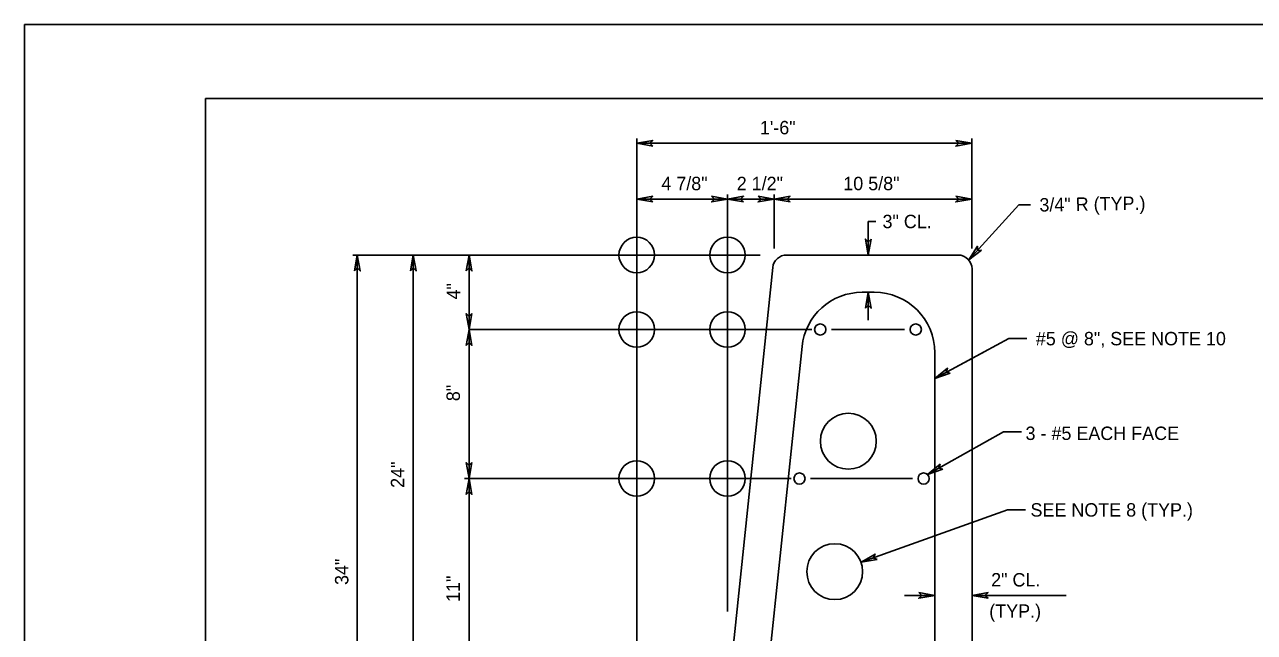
# Model space of a CAD drawing. Extents: x -32.9 to -15.8, y -6.5 to 4.5.
# Drawn here: x -24.32 to -18.82, y 1.78 to 4.5 of the extents above; entities that cross this region are included whole.
import ezdxf

# ---------------------------------------------------------------- set-up
doc = ezdxf.new("R2010")
doc.units = 0
for name, color, linetype in [('ANNO-WOUT', 7, 'Continuous'), ('BORD-LINE', 7, 'Continuous'), ('DETL-DIMS', 7, 'Continuous'), ('DETL-NOTE', 7, 'Continuous'), ('Level 10', 7, 'Continuous'), ('Level 12', 7, 'Continuous'), ('SUPR-PARA_P', 7, 'Continuous'), ('SUPR-RFRC', 7, 'Continuous'), ('USER-CLIP', 7, 'Continuous')]:
    doc.layers.add(name, color=color, linetype=linetype)

msp = doc.modelspace()

# ---------------------------------------------------------------- linework, layer by layer
at = {"layer": 'ANNO-WOUT'}
for centre in [(-21.5854, 3.4724), (-21.1791, 3.4724), (-21.5854, 3.1391), (-21.1791, 3.1391), (-21.5854, 2.4724), (-21.1791, 2.4724)]:
    msp.add_circle(centre, 0.0795, dxfattribs=at)
at = {"layer": 'BORD-LINE'}
msp.add_lwpolyline([(-23.5151, 4.1733), (-16.1409, 4.1733), (-16.1409, -6.1798), (-23.5151, -6.1798)], close=True, dxfattribs=at)
at = {"layer": 'DETL-DIMS'}
for p, q in [((-21.5854, 3.9724), (-21.5139, 3.9851)), ((-21.5854, 3.9724), (-21.5139, 3.9599)), ((-21.5274, 3.9724), (-21.5139, 3.9851)), ((-21.5139, 3.9599), (-21.5274, 3.9724)), ((-20.0867, 3.9724), (-20.1582, 3.985)), ((-20.1582, 3.985), (-20.1447, 3.9724)), ((-20.0867, 3.9724), (-20.1582, 3.9598)), ((-20.1447, 3.9724), (-20.1582, 3.9598)), ((-21.5854, 3.7224), (-21.5139, 3.7351)), ((-21.5854, 3.7224), (-21.5139, 3.7099)), ((-21.5274, 3.7224), (-21.5139, 3.7351)), ((-21.5139, 3.7099), (-21.5274, 3.7224)), ((-21.1791, 3.7224), (-21.2506, 3.735)), ((-21.2506, 3.735), (-21.2371, 3.7224)), ((-21.1791, 3.7224), (-21.2506, 3.7098)), ((-21.2371, 3.7224), (-21.2506, 3.7098)), ((-21.1791, 3.7224), (-21.1076, 3.7351)), ((-21.1791, 3.7224), (-21.1076, 3.7099)), ((-21.1211, 3.7224), (-21.1076, 3.7351)), ((-21.1076, 3.7099), (-21.1211, 3.7224)), ((-20.9708, 3.7224), (-21.0423, 3.735)), ((-21.0423, 3.735), (-21.0288, 3.7224)), ((-20.9708, 3.7224), (-21.0423, 3.7098)), ((-21.0288, 3.7224), (-21.0423, 3.7098)), ((-20.9708, 3.7224), (-20.8993, 3.7351)), ((-20.9708, 3.7224), (-20.8993, 3.7099)), ((-20.9128, 3.7224), (-20.8993, 3.7351)), ((-20.8993, 3.7099), (-20.9128, 3.7224)), ((-20.0867, 3.7224), (-20.1582, 3.735)), ((-20.1582, 3.735), (-20.1447, 3.7224)), ((-20.0867, 3.7224), (-20.1582, 3.7098)), ((-20.1447, 3.7224), (-20.1582, 3.7098)), ((-20.5497, 3.4724), (-20.5624, 3.544)), ((-20.5497, 3.5304), (-20.5624, 3.544)), ((-20.5497, 3.4724), (-20.5372, 3.5439)), ((-20.5372, 3.5439), (-20.5497, 3.5304)), ((-22.8354, 3.4724), (-22.8479, 3.401)), ((-22.8354, 3.4724), (-22.8227, 3.4009)), ((-22.5854, 3.4724), (-22.5979, 3.401)), ((-22.5854, 3.4724), (-22.5727, 3.4009)), ((-22.3354, 3.4724), (-22.3479, 3.401)), ((-22.3354, 3.4724), (-22.3227, 3.4009)), ((-20.1, 3.4501), (-20.0612, 3.5115)), ((-20.1, 3.4501), (-20.0426, 3.4945)), ((-20.0609, 3.493), (-20.0612, 3.5115)), ((-20.0426, 3.4945), (-20.0609, 3.493)), ((-22.8479, 3.401), (-22.8354, 3.4144)), ((-22.8354, 3.4144), (-22.8227, 3.4009)), ((-22.5979, 3.401), (-22.5854, 3.4144)), ((-22.5854, 3.4144), (-22.5727, 3.4009)), ((-22.3479, 3.401), (-22.3354, 3.4144)), ((-22.3354, 3.4144), (-22.3227, 3.4009)), ((-20.5497, 3.3058), (-20.5623, 3.2343)), ((-20.5497, 3.3058), (-20.5371, 3.2343)), ((-20.5623, 3.2343), (-20.5497, 3.2478)), ((-20.5497, 3.2478), (-20.5371, 3.2343)), ((-22.3354, 3.1391), (-22.3481, 3.2106)), ((-22.3354, 3.1971), (-22.3481, 3.2106)), ((-22.3354, 3.1391), (-22.3229, 3.2106)), ((-22.3229, 3.2106), (-22.3354, 3.1971)), ((-22.3354, 3.1391), (-22.3479, 3.0676)), ((-22.3354, 3.1391), (-22.3227, 3.0676)), ((-22.3479, 3.0676), (-22.3354, 3.0811)), ((-22.3354, 3.0811), (-22.3227, 3.0676)), ((-20.2519, 2.9205), (-20.1949, 2.9655)), ((-20.2519, 2.9205), (-20.1949, 2.9655)), ((-20.2519, 2.9205), (-20.183, 2.9433)), ((-20.2519, 2.9205), (-20.183, 2.9433)), ((-20.2008, 2.9479), (-20.1949, 2.9655)), ((-20.2008, 2.9479), (-20.1949, 2.9655)), ((-20.183, 2.9433), (-20.2008, 2.9479)), ((-20.183, 2.9433), (-20.2008, 2.9479)), ((-22.3354, 2.4724), (-22.3481, 2.544)), ((-22.3354, 2.5304), (-22.3481, 2.544)), ((-22.3354, 2.4724), (-22.3229, 2.5439)), ((-22.3229, 2.5439), (-22.3354, 2.5304)), ((-20.2844, 2.4901), (-20.2283, 2.5363)), ((-20.2339, 2.5187), (-20.2283, 2.5363)), ((-20.2844, 2.4901), (-20.216, 2.5144)), ((-20.216, 2.5144), (-20.2339, 2.5187)), ((-22.3354, 2.4724), (-22.3479, 2.401)), ((-22.3354, 2.4724), (-22.3227, 2.4009)), ((-22.3479, 2.401), (-22.3354, 2.4144)), ((-22.3354, 2.4144), (-22.3227, 2.4009)), ((-20.582, 2.0979), (-20.5189, 2.134)), ((-20.582, 2.0979), (-20.5104, 2.1102)), ((-20.5274, 2.1175), (-20.5189, 2.134)), ((-20.5104, 2.1102), (-20.5274, 2.1175)), ((-20.252, 1.9493), (-20.3236, 1.9366)), ((-20.31, 1.9493), (-20.3236, 1.9366)), ((-20.252, 1.9493), (-20.3236, 1.9366)), ((-20.31, 1.9493), (-20.3236, 1.9366)), ((-20.252, 1.9493), (-20.3235, 1.9618)), ((-20.3235, 1.9618), (-20.31, 1.9493)), ((-20.252, 1.9493), (-20.3235, 1.9618)), ((-20.3235, 1.9618), (-20.31, 1.9493)), ((-20.0854, 1.9493), (-20.0139, 1.962)), ((-20.0854, 1.9493), (-20.0139, 1.962)), ((-20.0854, 1.9493), (-20.0139, 1.9368)), ((-20.0854, 1.9493), (-20.0139, 1.9368)), ((-20.0274, 1.9493), (-20.0139, 1.962)), ((-20.0274, 1.9493), (-20.0139, 1.962)), ((-20.0139, 1.9368), (-20.0274, 1.9493)), ((-20.0139, 1.9368), (-20.0274, 1.9493))]:
    msp.add_line(p, q, dxfattribs=at)
for points in [[(-21.5139, 3.9599), (-21.5854, 3.9724), (-21.5139, 3.9851), (-21.5274, 3.9724)], [(-20.1582, 3.985), (-20.0867, 3.9724), (-20.1582, 3.9598), (-20.1447, 3.9724)], [(-21.5139, 3.7099), (-21.5854, 3.7224), (-21.5139, 3.7351), (-21.5274, 3.7224)], [(-21.2506, 3.735), (-21.1791, 3.7224), (-21.2506, 3.7098), (-21.2371, 3.7224)], [(-21.1076, 3.7099), (-21.1791, 3.7224), (-21.1076, 3.7351), (-21.1211, 3.7224)], [(-21.0423, 3.735), (-20.9708, 3.7224), (-21.0423, 3.7098), (-21.0288, 3.7224)], [(-20.8993, 3.7099), (-20.9708, 3.7224), (-20.8993, 3.7351), (-20.9128, 3.7224)], [(-20.1582, 3.735), (-20.0867, 3.7224), (-20.1582, 3.7098), (-20.1447, 3.7224)], [(-20.5372, 3.5439), (-20.5497, 3.4724), (-20.5624, 3.544), (-20.5497, 3.5304)], [(-22.8479, 3.401), (-22.8354, 3.4724), (-22.8227, 3.4009), (-22.8354, 3.4144)], [(-22.5979, 3.401), (-22.5854, 3.4724), (-22.5727, 3.4009), (-22.5854, 3.4144)], [(-22.3479, 3.401), (-22.3354, 3.4724), (-22.3227, 3.4009), (-22.3354, 3.4144)], [(-20.0426, 3.4945), (-20.1, 3.4501), (-20.0612, 3.5115), (-20.0609, 3.493)], [(-20.5623, 3.2343), (-20.5497, 3.3058), (-20.5371, 3.2343), (-20.5497, 3.2478)], [(-22.3229, 3.2106), (-22.3354, 3.1391), (-22.3481, 3.2106), (-22.3354, 3.1971)], [(-22.3479, 3.0676), (-22.3354, 3.1391), (-22.3227, 3.0676), (-22.3354, 3.0811)], [(-20.183, 2.9433), (-20.2519, 2.9205), (-20.1949, 2.9655), (-20.2008, 2.9479)], [(-20.183, 2.9433), (-20.2519, 2.9205), (-20.1949, 2.9655), (-20.2008, 2.9479)], [(-22.3229, 2.5439), (-22.3354, 2.4724), (-22.3481, 2.544), (-22.3354, 2.5304)], [(-20.216, 2.5144), (-20.2844, 2.4901), (-20.2283, 2.5363), (-20.2339, 2.5187)], [(-22.3479, 2.401), (-22.3354, 2.4724), (-22.3227, 2.4009), (-22.3354, 2.4144)], [(-20.5104, 2.1102), (-20.582, 2.0979), (-20.5189, 2.134), (-20.5274, 2.1175)], [(-20.3235, 1.9618), (-20.252, 1.9493), (-20.3236, 1.9366), (-20.31, 1.9493)], [(-20.3235, 1.9618), (-20.252, 1.9493), (-20.3236, 1.9366), (-20.31, 1.9493)], [(-20.0139, 1.9368), (-20.0854, 1.9493), (-20.0139, 1.962), (-20.0274, 1.9493)], [(-20.0139, 1.9368), (-20.0854, 1.9493), (-20.0139, 1.962), (-20.0274, 1.9493)]]:
    msp.add_lwpolyline(points, close=True, dxfattribs=at)
at = {"layer": 'Level 10'}
for p, q in [((-21.5854, 0.9491), (-21.5854, 3.9933)), ((-21.5854, 3.9724), (-20.0867, 3.9724)), ((-20.0867, 3.5017), (-20.0867, 3.9933)), ((-21.1791, 1.877), (-21.1791, 3.7433)), ((-20.9708, 3.5012), (-20.9708, 3.7433)), ((-21.5854, 3.7224), (-21.1791, 3.7224)), ((-21.1791, 3.7224), (-20.9708, 3.7224)), ((-20.9708, 3.7224), (-20.0867, 3.7224)), ((-19.8753, 3.6968), (-20.1, 3.4501)), ((-19.8753, 3.6968), (-19.824, 3.6968)), ((-20.5497, 3.4724), (-20.5497, 3.6224)), ((-20.5497, 3.6224), (-20.5159, 3.6224)), ((-21.0337, 3.4724), (-22.8562, 3.4724)), ((-22.8354, 3.4724), (-22.8354, 0.6391)), ((-22.5854, 1.4753), (-22.5854, 3.4724)), ((-22.3354, 3.1391), (-22.3354, 3.4724)), ((-20.5497, 3.1808), (-20.5497, 3.3058)), ((-22.3354, 2.4724), (-22.3354, 3.1391)), ((-20.8022, 3.1391), (-22.3354, 3.1391)), ((-21.627, 3.1391), (-21.8865, 3.1391)), ((-21.2208, 3.1391), (-21.5437, 3.1391)), ((-20.3869, 3.1391), (-20.7147, 3.1391)), ((-19.9211, 3.0983), (-20.2523, 2.9203)), ((-19.9211, 3.0983), (-19.8401, 3.0983)), ((-20.025, 3.0424), (-20.2523, 2.9203)), ((-19.9452, 2.6817), (-20.2844, 2.4901)), ((-19.9452, 2.6817), (-19.8642, 2.6817)), ((-22.3562, 2.4724), (-20.8948, 2.4724)), ((-22.3354, 1.5558), (-22.3354, 2.4724)), ((-20.8073, 2.4724), (-20.352, 2.4724)), ((-19.9274, 2.3322), (-20.582, 2.0979)), ((-19.9274, 2.3322), (-19.8463, 2.3322)), ((-20.3872, 1.9493), (-20.252, 1.9493)), ((-20.3872, 1.9493), (-20.252, 1.9493)), ((-19.6645, 1.9493), (-20.0854, 1.9493))]:
    msp.add_line(p, q, dxfattribs=at)
at = {"layer": 'SUPR-PARA_P'}
for p, q in [((-20.9145, 3.4724), (-20.1479, 3.4724)), ((-21.157, 1.6879), (-20.9767, 3.4164)), ((-20.0854, 0.6391), (-20.0854, 3.4099))]:
    msp.add_line(p, q, dxfattribs=at)
for centre in [(-20.6388, 2.6391), (-20.6997, 2.0558)]:
    msp.add_circle(centre, 0.125, dxfattribs=at)
for centre, start, end in [((-20.9145, 3.4099), 90, 174.0468), ((-20.1479, 3.4099), 0, 90)]:
    msp.add_arc(centre, 0.0625, start, end, dxfattribs=at)
at = {"layer": 'SUPR-RFRC'}
for p, q in [((-20.5766, 3.3058), (-20.5229, 3.3058)), ((-21.2812, -1.1109), (-20.846, 3.063)), ((-20.252, -1.1109), (-20.252, 3.0349))]:
    msp.add_line(p, q, dxfattribs=at)
for centre in [(-20.7647, 3.1391), (-20.3369, 3.1391), (-20.8573, 2.4724), (-20.302, 2.4724)]:
    msp.add_circle(centre, 0.025, dxfattribs=at)
for centre, start, end in [((-20.5766, 3.0349), 90, 174.0468), ((-20.5229, 3.0349), 0, 90)]:
    msp.add_arc(centre, 0.2708, start, end, dxfattribs=at)
at = {"layer": 'USER-CLIP'}
msp.add_lwpolyline([(-15.824, 4.5033), (-24.324, 4.5033), (-24.324, -6.4967), (-15.824, -6.4967)], close=True, dxfattribs=at)

# ---------------------------------------------------------------- texts
at = {"layer": 'DETL-NOTE'}
msp.add_text('3" CL.', height=0.06001, dxfattribs=at).set_placement((-20.4859, 3.5924))
at = {"layer": 'Level 12'}
for s, p in [('1\'-6"', (-21.0344, 4.0124)), ('4 7/8"', (-21.4753, 3.7624)), ('2 1/2"', (-21.1381, 3.7623)), ('10 5/8"', (-20.6614, 3.7624)), ('#5 @ 8", SEE NOTE 10', (-19.8, 3.0683)), ('3 - #5 EACH FACE', (-19.8461, 2.6448)), ('SEE NOTE 8 (TYP.)', (-19.8239, 2.302)), ('2" CL.', (-20, 1.9893)), ('(TYP.)', (-20.0084, 1.8493))]:
    msp.add_text(s, height=0.06001, dxfattribs=at).set_placement(p)
for s, rotation, p in [('3/4" R (TYP.)', 1, (-19.7834, 3.6667)), ('4"', 90, (-22.3753, 3.2733)), ('8"', 90, (-22.3765, 2.8184)), ('24"', 90, (-22.6254, 2.4305)), ('34"', 90, (-22.8753, 1.9961)), ('11"', 90, (-22.3765, 1.9203))]:
    msp.add_text(s, height=0.06001, rotation=rotation, dxfattribs=at).set_placement(p)

doc.saveas('drawing.dxf')
